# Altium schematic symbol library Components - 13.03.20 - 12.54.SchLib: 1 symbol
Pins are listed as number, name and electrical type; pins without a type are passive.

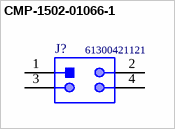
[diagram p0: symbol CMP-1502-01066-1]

## CMP-1502-01066-1
designator J?, comment 61300421121
THT Vertical Pin Header WR-PHD, Pitch 2.54 mm, Dual Row, 4 pins; Manufacturer: Wurth Elektronik; Working Voltage: 250VAC; Contact Resistance: 20mOhm; Pitch: 2.54mm; Rated Current: 3A; Withstanding Voltage: 500VAC; Pin Number: 4; Gender: Male
footprint 61300421121 (Pin Header, pitch 2.54 mm, THT, Vertical, dual row, 4p)
pins: 1, 2, 3, 4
